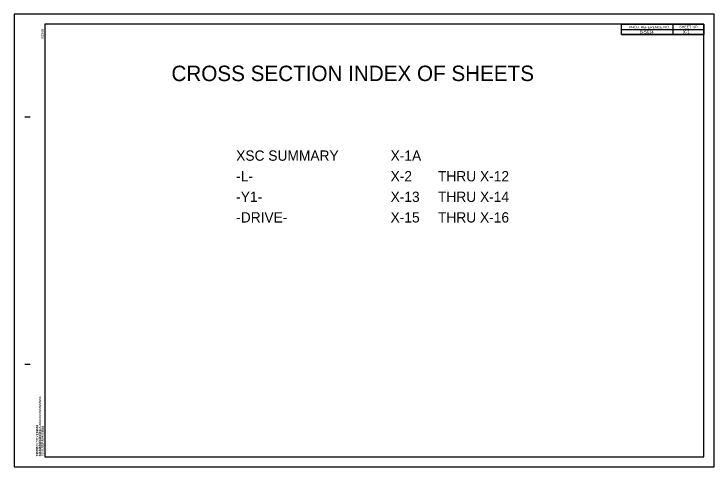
# Model space of a CAD drawing. Extents: x -15 to 325, y -225 to -5.
import ezdxf

# ---------------------------------------------------------------- set-up
doc = ezdxf.new("R2010")
doc.units = 0
for name, color, linetype in [('Sheet Block Title CELL', 7, 'Continuous'), ('Sheet Cross Section CELL', 7, 'Continuous'), ('Sheet Data Field CELL', 7, 'Continuous'), ('Sheet Summary Combination CELL', 7, 'Continuous'), ('Stewart Plot Border Xerox6279 and LJ5000', 7, 'Continuous')]:
    doc.layers.add(name, color=color, linetype=linetype)

msp = doc.modelspace()

# ---------------------------------------------------------------- linework, layer by layer
at = {"layer": 'Sheet Block Title CELL'}
for p, q in [((305, -10.01), (305, -15.01)), ((280, -12.51), (320, -12.51)), ((280, -15.01), (320, -15.01))]:
    msp.add_line(p, q, dxfattribs=at)
msp.add_lwpolyline([(280, -10), (320, -10), (320, -15.01), (280, -15.01)], close=True, dxfattribs=at)
at = {"layer": 'Sheet Cross Section CELL'}
for p, q in [((-9.8, -55), (-7.3, -55)), ((-9.7, -55), (-7.2, -55)), ((-9.8, -175), (-7.3, -175)), ((-9.7, -175), (-7.2, -175)), ((0, -220), (0, -220)), ((0, -220), (0, -220)), ((0, -220), (0, -220)), ((0, -220), (0, -220)), ((0, -220), (0, -220)), ((0, -220), (0, -220)), ((0, -220), (0, -220))]:
    msp.add_line(p, q, dxfattribs=at)
msp.add_lwpolyline([(320, -10), (0, -10), (0, -220), (320, -220)], close=True, dxfattribs=at)
at = {"layer": 'Stewart Plot Border Xerox6279 and LJ5000'}
msp.add_lwpolyline([(-15, -225), (325, -225), (325, -5), (-15, -5)], close=True, dxfattribs=at)

# ---------------------------------------------------------------- texts
at = {"layer": 'Sheet Block Title CELL'}
for s, p in [('PROJ. REFERENCE NO.', (283.77, -12.01)), ('SHEET NO.', (308.19, -11.88))]:
    msp.add_text(s, height=1.25, dxfattribs=at).set_placement(p)
at = {"layer": 'Sheet Cross Section CELL'}
for s, p in [('8/23/99', (-0.65, -17)), ('$$$$$$$$$$$$$$$$DGN$$$$$$$$$$$$$$$$', (-1.88, -219.82)), ('$$$$$$SYSTIME$$$$$', (-3.26, -219.82)), ('$$$$USERNAME$$$$', (-0.62, -219.77))]:
    msp.add_text(s, height=1.05, rotation=90, dxfattribs=at).set_placement(p)
at = {"layer": 'Sheet Data Field CELL'}
for s, p in [('B-5614', (289.02, -14.51)), ('X-1', (309.91, -14.5))]:
    msp.add_text(s, height=1.5, dxfattribs=at).set_placement(p)
at = {"layer": 'Sheet Summary Combination CELL'}
msp.add_text('CROSS SECTION INDEX OF SHEETS', height=7.5, rotation=0.0119, dxfattribs=at).set_placement((61.49, -37.6))
for s, p in [('XSC SUMMARY', (92.92, -76.27)), ('X-1A', (167.92, -76.27)), ('-L-', (92.92, -86.27)), ('X-2', (167.92, -86.27)), ('THRU X-12', (190.92, -86.27)), ('-Y1-', (92.92, -96.27)), ('X-13', (167.92, -96.27)), ('THRU X-14', (190.92, -96.27)), ('-DRIVE-', (92.92, -106.27)), ('X-15', (167.92, -106.27)), ('THRU X-16', (190.92, -106.27))]:
    msp.add_text(s, height=5, dxfattribs=at).set_placement(p)

doc.saveas('drawing.dxf')
